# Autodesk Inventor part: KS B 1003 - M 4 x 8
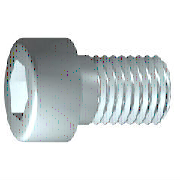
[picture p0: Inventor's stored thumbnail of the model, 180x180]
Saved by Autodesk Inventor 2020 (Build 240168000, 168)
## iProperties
Created: 2019-01
Part Number: KS B 1003 - M 4 x 8
Material: Acier, doux
Description: Vis à tôle à tête hexagonale
Document SubType Name: Modeling
Standard: KS B 1003
Designer: bruno
Standards Organization: KS
Language: fr-FR
Size Designation: M 4 x 8
Categories: <MemberInstance><Categories><Category DisplayName="Visserie" InternalName="e4da775c-781d-43d5-af7c-5136215cf5a6" Mnemonic="FSTN"><Category DisplayName="Vis" Int
Density: 7.85 g/cm^3
Appearance: Semi-poli
IsCustomPart: 0
Author: bruno
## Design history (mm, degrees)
sketch "Esquisse1"
  geometry: L1 (-1, 0)-(8, 0); L2 (8, 0)-(8, 2); L3 (8, 2)-(1.75, 2); L4 (1.75, 2)-(1.32, 2); L5 (1.32, 2)-(0, 2); L6 (0, 2)-(0, 3.5); L7 (0, 3.5)-(-4, 3.5); L8 (-4, 3.5)-(-4, 1.732); L9 (-4, 1.732)-(-2, 1.732); L10 (-2, 1.732)-(-1, 0); L11 (-6.4, 0)-(10.4, 0) reference; L12 (0, -0.7)-(0, 4.2) reference; L13 (1.75, 2)-(0, 2)
  constraints: 22 end point, 6 parallel, 2 collinear, 2 perpendicular, 1 horizontal, 1 point on line
  dimensions: "d1" = 6.25 distance from line of L3.end L2 (= GEL); "d2" = 0.42952 distance of L4.end L3.end (computed from GAL); "d3" = 4 distance between parallel lines of L8 L6 (= KOH); "d4" = 2 distance of L8.end L9.end (= INTI); "d5" = 60 deg angle of L10 L1; "d6" = 4 diameter of L3 L1 (= GD); "d7" = 4 diameter of L5 L1 (= BDM); "d8" = 3.4641 diameter of L9 L1 (= 1.1547 x SW); "d9" = 7 diameter of L7 L1 (= KOD); "d26" = 8 distance between parallel lines of L12 L2 (= NLG)
revolve "Corps" sketch "Esquisse1" stored, may be unused: angle "d10" = 90 deg
sketch "Esquisse2"
  geometry: L1 (0, -4.9)-(0, 4.9) reference; L2 (-4.9, 0)-(4.9, 0) reference; L3 (1.732, 0)-(0.866, -1.5); L4 (0.866, -1.5)-(-0.866, -1.5); L5 (-0.866, -1.5)-(-1.732, 0); L6 (-1.732, 0)-(-0.866, 1.5); L7 (-0.866, 1.5)-(0.866, 1.5); L8 (0.866, 1.5)-(1.732, 0); 2 further points
  constraints: 12 end point, 1 coincident, 1 horizontal alignment, 1 point on line, 12 other
extrude "Rainure" join sketch "Esquisse2" stored distance "d11" = 10; taper "d12" = 0 deg
workplane "Work Plane1"
fillet "Fillet2" dims "d30" = 0.1 (= R)
body "Solid1"
fillet "Congé1" dims "d17" = 0.4 (= RR)
feature "Filetage" dims "d13" = 6.25 (= GEL), "d14" = 0
chamfer "Chanfrein1" distance "d15" = 0.42941 (= -0.5 x SPD + 0.5 x GD); stored, may be unused: second distance "d16" = 0.42941 (= GUL), angle "d27" = 45 deg
other parameters: "GD" = 4 (= NND) [user parameter; used in 2 equation terms], "NLG" = 8 [user parameter; used in 1 equation term], "GEL" = 6.25 [user parameter; used in 2 equation terms], "KOD" = 7 [user parameter; used in 1 equation term], "KOH" = 4 [user parameter; used in 1 equation term], "INTI" = 2 [user parameter; used in 1 equation term], "GAL" = 0.42941 (= 0.61345 x PTC) [user parameter; used in 1 equation term], "GUL" = 0.42941 (= 0.61345 x PTC) [user parameter; used in 1 equation term], "BDM" = 4 (= NND) [user parameter; used in 1 equation term], "SW" = 3 [user parameter; used in 2 equation terms], "RR" = 0.4 [user parameter; used in 1 equation term], "SPD" = 3.14117 (= NND - 1.2269 x PTC) [user parameter; used in 1 equation term], "d19" = 0, "d28" = 0, "d29" = 0, "R" = 0.1 [user parameter; used in 1 equation term], "PHH" = 0.2 [user parameter], "GD1" = 3.14117 (= THREADDIA - 1.2269 x PTC) [user parameter], "THREADDIA" = 4 [user parameter; used in 1 equation term], "FAWI" = 45 deg [user parameter], "TPU" = 14.28571 (computed from PTC) [user parameter], "PTC" = 0.7 [user parameter; used in 5 equation terms], "NND" = 4 [user parameter; used in 3 equation terms], "TOA" = 30 deg [user parameter], "E0" = 3.465 (= 1.155 x SW) [user parameter]
